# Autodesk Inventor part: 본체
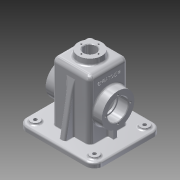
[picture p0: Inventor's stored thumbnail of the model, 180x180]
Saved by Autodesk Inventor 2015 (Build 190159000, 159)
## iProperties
Created: 2016-02
Part Number: 본체
Material: 알루미늄 6061
Document SubType Name: Modeling
Designer: Administrator
Density: 2.7 g/cm^3
Appearance: 알루미늄 - 평지
Mass: 856.212 g
Surface Area: 918.664 cm^2
Volume: 317.116 cm^3
Author: Administrator
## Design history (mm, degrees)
sketch "스케치1"
  geometry: L1 (-65, -57.5)-(65, -57.5); L2 (65, -57.5)-(65, 57.5); L3 (65, 57.5)-(-65, 57.5); L4 (-65, 57.5)-(-65, -57.5); L5 (-65, -57.5)-(65, 57.5); L6 (65, -57.5)-(-65, 57.5); 1 further point
  constraints: 12 end point, 2 midpoint, 2 parallel, 1 horizontal, 1 perpendicular
  dimensions: "d0" = 130 distance of L2.end L3.end; "d1" = 115 distance of L1.end L2.end
extrude "돌출1" new body sketch "스케치1" distance "d2" = 8; taper "d3" = 0 deg
sketch "스케치2"
  geometry: L1 (-60, -52.5)-(60, -52.5); L2 (60, -52.5)-(60, 52.5); L3 (60, 52.5)-(-60, 52.5); L4 (-60, 52.5)-(-60, -52.5); L5 (-60, -52.5)-(60, 52.5); L6 (60, -52.5)-(-60, 52.5); 1 further point
  constraints: 12 end point, 2 midpoint, 2 parallel, 1 horizontal, 1 perpendicular
  dimensions: "d4" = 120 distance of L2.end L3.end; "d5" = 105 distance of L1.end L2.end
extrude "돌출2" join sketch "스케치2" distance "d6" = 2; taper "d7" = 0 deg
sketch "스케치4"
  geometry: L1 (-65, -57.5)-(-65, 57.5) reference; L2 (-65, 57.5)-(65, 57.5) reference; L3 (65, 57.5)-(65, -57.5) reference; L4 (65, -57.5)-(-65, -57.5) reference; L5 (-32.5, -32.5)-(32.5, -32.5); L6 (32.5, -32.5)-(32.5, 32.5); L7 (32.5, 32.5)-(-32.5, 32.5); L8 (-32.5, 32.5)-(-32.5, -32.5); L9 (-32.5, -32.5)-(32.5, 32.5); L10 (32.5, -32.5)-(-32.5, 32.5); L11 (-5, 32.5)-(-5, 47.5); L12 (-5, 47.5)-(5, 47.5); L13 (5, 47.5)-(5, 32.5); L14 (-5, -32.5)-(-5, -47.5); L15 (-5, -47.5)-(5, -47.5); L16 (5, -47.5)-(5, -32.5); L17 (32.5, 3)-(42.5, 3); L18 (42.5, 3)-(42.5, -3); L19 (42.5, -3)-(32.5, -3); L20 (-32.5, 3)-(-42.5, 3); L21 (-42.5, 3)-(-42.5, -3); L22 (-42.5, -3)-(-32.5, -3); 8 further points
  constraints: 36 end point, 9 midpoint, 8 perpendicular, 8 point on line, 4 horizontal, 2 horizontal alignment, 2 parallel, 2 vertical, 2 vertical alignment
  dimensions: "d8" = 65 distance of L6.end L7.end; "d9" = 65 distance of L5.end L6.end; "d10" = 15 distance between parallel lines of L7 L12; "d11" = 10 distance of L11.end L12.end; "d12" = 15 distance between parallel lines of L15 L5; "d13" = 10 distance of L14.end L15.end; "d14" = 10 distance between parallel lines of L6 L18; "d15" = 6 distance of L17.end L18.end; "d16" = 6 distance of L20.end L21.end; "d17" = 10 distance between parallel lines of L21 L8
  node "절단 모서리 투영1"
extrude "돌출3" join sketch "스케치4" distance "d18" = 67.5; taper "d19" = 0 deg
extrude "돌출4" join sketch "스케치4" distance "d20" = 60; taper "d21" = 0 deg
sketch "스케치5"
  geometry: L1 (-75.5, -20)-(-77.5, -20) reference; L2 (-77.5, -20)-(-77.5, 85) reference; L3 (-77.5, 85)-(-75.5, 85) reference; L4 (-75.5, 85)-(-75.5, 90) reference; L5 (-75.5, 90)-(-67.5, 90) reference; L6 (-67.5, 90)-(-67.5, 65) reference; L7 (-67.5, 65)-(-67.5, 35.5) reference; L8 (-67.5, 35.5)-(-7.5, 35.5) reference; L9 (-7.5, 35.5)-(-7.5, 29.5) reference; L10 (-7.5, 29.5)-(-67.5, 29.5) reference; L11 (-67.5, 29.5)-(-67.5, 0) reference; L12 (-67.5, 0)-(-67.5, -25) reference; L13 (-67.5, -25)-(-75.5, -25) reference; L14 (-75.5, -25)-(-75.5, -20) reference; L15 (-67.5, 65)-(0, 65) reference; L16 (0, 65)-(0, 0) reference; L17 (0, 0)-(-67.5, 0) reference; C1 r 27.5 at (-22.5, 32.5); 1 further point
  constraints: 1 centre point, 1 horizontal alignment
  dimensions: "d22" = 55 diameter of C1; "d124" = 53 distance of point (-75.5, 32.5) C1.centre
extrude "돌출5" join sketch "스케치5" distance "d23" = 15; taper "d25" = 0 deg; dims "d24" = 80, "d26" = 0
sketch "스케치6"
  geometry: L1 (-32.5, -15.811)-(-47.5, -15.811) reference; L2 (-32.5, 15.811)-(-32.5, 32.5) reference; L3 (-32.5, -32.5)-(-32.5, -15.811) reference; L4 (32.5, -32.5)-(-32.5, -32.5) reference; L5 (32.5, -15.811)-(32.5, -32.5) reference; L6 (-32.5, 32.5)-(32.5, 32.5) reference; L7 (32.5, 32.5)-(32.5, 15.811) reference; L8 (-32.5, -32.5)-(32.5, -32.5); L9 (32.5, -32.5)-(32.5, 32.5); L10 (32.5, 32.5)-(-32.5, 32.5); L11 (-32.5, 32.5)-(-32.5, -32.5); L12 (-32.5, -32.5)-(32.5, 32.5); L13 (32.5, -32.5)-(-32.5, 32.5); L14 (-47.5, 15.811)-(-32.5, 15.811) reference; L15 (-32.5, 15.811)-(32.5, 15.811) reference; L16 (32.5, 15.811)-(47.5, 15.811) reference; L17 (47.5, 15.811)-(47.5, -15.811) reference; L18 (47.5, -15.811)-(32.5, -15.811) reference; L19 (32.5, -15.811)-(-32.5, -15.811) reference; L20 (-47.5, -15.811)-(-47.5, 15.811) reference; 2 further points
  constraints: 12 end point, 2 midpoint, 2 parallel, 1 horizontal, 1 perpendicular
extrude "돌출6" join sketch "스케치6" distance "d27" = 32.5; taper "d28" = 0 deg
sketch "스케치7"
  geometry: L1 (-32.5, -32.5)-(-32.5, 32.5) reference; L2 (-32.5, 32.5)-(32.5, 32.5) reference; L3 (32.5, 32.5)-(32.5, -32.5) reference; L4 (32.5, -32.5)-(-32.5, -32.5) reference; C1 r 20 at (0, 0); 1 further point
  constraints: 1 centre point, 1 coincident
  dimensions: "d29" = 40 diameter of C1
extrude "돌출7" join sketch "스케치7" distance "d30" = 10; taper "d31" = 0 deg
extrude "돌출8" join sketch "스케치4" distance "d32" = 110; taper "d33" = 0 deg
feature "면 기울기1" dims angle "d34" = 10 deg
feature "면 기울기2" dims angle "d35" = 10 deg
sketch "스케치10"
  geometry: L1 (-60, -52.5)-(-60, 52.5) reference; L2 (-60, 52.5)-(60, 52.5) reference; L3 (60, 52.5)-(60, -52.5) reference; L4 (60, -52.5)-(-60, -52.5) reference; L5 (27.5, 27.5)-(-27.5, 27.5); L6 (-27.5, 27.5)-(-27.5, -27.5); L7 (-27.5, -27.5)-(27.5, -27.5); L8 (27.5, -27.5)-(27.5, 27.5); L9 (27.5, 27.5)-(-27.5, -27.5); L10 (-27.5, 27.5)-(27.5, -27.5); 1 further point
  constraints: 12 end point, 2 midpoint, 2 parallel, 1 horizontal, 1 perpendicular
  dimensions: "d36" = 55 distance of L6.end L7.end; "d37" = 55 distance of L5.end L6.end
extrude "돌출9" cut sketch "스케치10" distance "d38" = 105; taper "d39" = 0 deg
sketch "스케치11"
  geometry: L1 (-53, -52.5)-(-55, -52.5) reference; L2 (-55, -52.5)-(-55, 52.5) reference; L3 (-55, 52.5)-(-53, 52.5) reference; L4 (-53, 52.5)-(-53, 57.5) reference; L5 (-53, 57.5)-(-45, 57.5) reference; L6 (-45, 57.5)-(-45, -57.5) reference; L7 (-45, -57.5)-(-53, -57.5) reference; L8 (-53, -57.5)-(-53, -52.5) reference; C1 r 27.5 at (0, 0) reference; C2 r 17.5 at (0, 0); 1 further point
  constraints: 1 centre point, 1 coincident
  dimensions: "d40" = 35 diameter of C2
extrude "돌출10" cut sketch "스케치11" distance "d41" = 17; taper "d42" = 0 deg
sketch "스케치12"
  geometry: L1 (55, -52.5)-(53, -52.5) reference; L2 (53, -52.5)-(53, -57.5) reference; L3 (53, -57.5)-(45, -57.5) reference; L4 (45, -57.5)-(45, 57.5) reference; L5 (45, 57.5)-(53, 57.5) reference; L6 (53, 57.5)-(53, 52.5) reference; L7 (53, 52.5)-(55, 52.5) reference; L8 (55, 52.5)-(55, -52.5) reference; C1 r 27.5 at (0, 0) reference; C2 r 17.5 at (0, 0); 1 further point
  constraints: 1 centre point, 1 coincident
  dimensions: "d43" = 35 diameter of C2
extrude "돌출11" cut sketch "스케치12" distance "d44" = 17; taper "d45" = 0 deg
sketch "스케치13"
  geometry: L1 (55, -52.5)-(53, -52.5) reference; L2 (53, -52.5)-(53, -57.5) reference; L3 (53, -57.5)-(45, -57.5) reference; L4 (45, -57.5)-(45, -32.5) reference; L5 (45, -32.5)-(-55, -32.5) reference; L6 (-55, -32.5)-(-55, 32.5) reference; L7 (-55, 32.5)-(45, 32.5) reference; L8 (45, 32.5)-(45, 57.5) reference; L9 (45, 57.5)-(53, 57.5) reference; L10 (53, 57.5)-(53, 52.5) reference; L11 (53, 52.5)-(55, 52.5) reference; L12 (55, 52.5)-(55, -52.5) reference; C1 r 17.5 at (0, 0) reference; C2 r 15 at (0, 0); 1 further point
  constraints: 1 centre point, 1 coincident
  dimensions: "d46" = 30 diameter of C2
extrude "돌출12" cut sketch "스케치13" stored distance "d47" = 17; taper "d48" = 0 deg
sketch "스케치14"
  geometry: C1 r 20 at (0, 0) reference; C2 r 10.5 at (0, 0); 1 further point
  constraints: 1 centre point, 1 coincident
  dimensions: "d49" = 21 diameter of C2
extrude "돌출13" cut sketch "스케치14" stored distance "d50" = 17; taper "d51" = 0 deg
sketch "스케치15"
  geometry: C1 r 10.5 at (0, 0) reference; C2 r 20 at (0, 0) reference; 5 further points
  constraints: 1 vertical alignment, 5 other
  dimensions: "d52" = 14.5 distance of point (0, 0) point (0, 14.5); "d55" = 360 deg dimension on point (0, 0) point (0, 14.5) (derived)
hole "구멍1" sketch "스케치15" at (0, 14.5), (-14.5, 0), (0, -14.5), (14.5, 0) diameter "d57" = 2.459; stored, may be unused: countersink angle "d61" = 90 deg, drill point angle "d63" = 118 deg; dims "d58" = 7, "d59" = 4, "d60" = 2, "d62" = 9
sketch "스케치16"
  geometry: L1 (-53, -52.5)-(-55, -52.5) reference; L2 (-55, -52.5)-(-55, 52.5) reference; L3 (-55, 52.5)-(-53, 52.5) reference; L4 (-53, 52.5)-(-53, 57.5) reference; L5 (-53, 57.5)-(-45, 57.5) reference; L6 (-45, 57.5)-(-45, -57.5) reference; L7 (-45, -57.5)-(-53, -57.5) reference; L8 (-53, -57.5)-(-53, -52.5) reference; C1 r 17.5 at (0, 0) reference; C2 r 27.5 at (0, 0) reference; 5 further points
  constraints: 1 horizontal alignment, 5 other
  dimensions: "d64" = 21 distance of C1.centre point (21, 0); "d67" = 360 deg dimension on C1.centre point (21, 0) (derived)
hole "구멍2" sketch "스케치16" at (21, 0), (0, 21), (-21, 0), (0, -21) diameter "d69" = 3.242; stored, may be unused: countersink angle "d73" = 90 deg, drill point angle "d75" = 118 deg; dims "d70" = 8, "d71" = 4, "d72" = 2, "d74" = 10
sketch "스케치17"
  geometry: L1 (55, -52.5)-(53, -52.5) reference; L2 (53, -52.5)-(53, -57.5) reference; L3 (53, -57.5)-(45, -57.5) reference; L4 (45, -57.5)-(45, 57.5) reference; L5 (45, 57.5)-(53, 57.5) reference; L6 (53, 57.5)-(53, 52.5) reference; L7 (53, 52.5)-(55, 52.5) reference; L8 (55, 52.5)-(55, -52.5) reference; C1 r 17.5 at (0, 0) reference; C2 r 27.5 at (0, 0) reference; 5 further points
  constraints: 1 horizontal alignment, 5 other
  dimensions: "d76" = 21 distance of C1.centre point (-21, 0); "d79" = 360 deg dimension on C1.centre point (-21, 0) (derived)
hole "구멍3" sketch "스케치17" at (-21, 0), (0, -21), (21, 0), (0, 21) diameter "d81" = 3.242; stored, may be unused: countersink angle "d85" = 90 deg, drill point angle "d87" = 118 deg; dims "d82" = 8, "d83" = 4, "d84" = 2, "d86" = 10
fillet "모깎기1" dims "d88" = 15
sketch "스케치18"
  geometry: L1 (-50, 57.5)-(50, 57.5) reference; L2 (65, 42.5)-(65, -42.5) reference; L3 (50, -57.5)-(-50, -57.5) reference; L4 (-65, -42.5)-(-65, 42.5) reference; L5 (27.5, -27.5)-(27.5, 27.5) reference; L6 (27.5, 27.5)-(-27.5, 27.5) reference; L7 (-27.5, 27.5)-(-27.5, -27.5) reference; L8 (-27.5, -27.5)-(27.5, -27.5) reference; L9 (-32.5, 3)-(-32.5, 32.5) reference; L10 (-32.5, 32.5)-(-5, 32.5) reference; L11 (-5, 32.5)-(-5, 47.5) reference; L12 (-5, 47.5)-(5, 47.5) reference; L13 (5, 47.5)-(5, 32.5) reference; L14 (5, 32.5)-(32.5, 32.5) reference; L15 (32.5, 32.5)-(32.5, 3) reference; L16 (32.5, 3)-(42.5, 3) reference; L17 (42.5, 3)-(42.5, -3) reference; L18 (42.5, -3)-(32.5, -3) reference; L19 (32.5, -3)-(32.5, -32.5) reference; L20 (32.5, -32.5)-(5, -32.5) reference; L21 (5, -32.5)-(5, -47.5) reference; L22 (5, -47.5)-(-5, -47.5) reference; L23 (-5, -47.5)-(-5, -32.5) reference; L24 (-5, -32.5)-(-32.5, -32.5) reference; L25 (-32.5, -32.5)-(-32.5, -3) reference; L26 (-32.5, -3)-(-42.5, -3) reference; L27 (-42.5, -3)-(-42.5, 3) reference; L28 (-42.5, 3)-(-32.5, 3) reference; C1 r 7.5 at (-50, 42.5); C2 r 7.5 at (50, 42.5); C3 r 7.5 at (50, -42.5); C4 r 7.5 at (-50, -42.5); A1 r 15 centre (-50, 42.5) between (-50, 57.5) and (-65, 42.5) reference; A2 r 15 centre (50, 42.5) between (65, 42.5) and (50, 57.5) reference; A3 r 15 centre (50, -42.5) between (50, -57.5) and (65, -42.5) reference; A4 r 15 centre (-50, -42.5) between (-65, -42.5) and (-50, -57.5) reference; 1 further point
  constraints: 4 centre point, 4 coincident
  dimensions: "d89" = 15 diameter of C1; "d90" = 15 diameter of C2; "d91" = 15 diameter of C3; "d92" = 15 diameter of C4
extrude "돌출14" join sketch "스케치18" distance "d93" = 3; taper "d94" = 0 deg
sketch "스케치19"
  geometry: L1 (-22.5, 15)-(-22.5, 70) reference; L2 (-22.5, 70)-(-77.5, 70) reference; L3 (-77.5, 70)-(-77.5, 15) reference; L4 (-77.5, 15)-(-22.5, 15) reference; L5 (-82.5, 45.5)-(-82.5, 75) reference; L6 (-82.5, 75)-(-55, 75) reference; L7 (-55, 75)-(-55, 89.471) reference; L8 (-55, 89.471)-(-45, 89.471) reference; L9 (-45, 89.471)-(-45, 75) reference; L10 (-45, 75)-(-17.5, 75) reference; L11 (-17.5, 75)-(-17.5, 45.5) reference; L12 (-17.5, 45.5)-(-7.5, 45.5) reference; L13 (-7.5, 45.5)-(-7.5, 39.5) reference; L14 (-7.5, 39.5)-(-17.5, 39.5) reference; L15 (-17.5, 39.5)-(-17.5, 10) reference; L16 (-17.5, 10)-(-45, 10) reference; L17 (-45, 10)-(-45, -4.471) reference; L18 (-45, -4.471)-(-55, -4.471) reference; L19 (-55, -4.471)-(-55, 10) reference; L20 (-55, 10)-(-82.5, 10) reference; L21 (-82.5, 10)-(-82.5, 39.5) reference; L22 (-82.5, 39.5)-(-92.5, 39.5) reference; L23 (-92.5, 39.5)-(-92.5, 45.5) reference; L24 (-92.5, 45.5)-(-82.5, 45.5) reference; C1 r 7.5 at (0, 0) reference; C2 r 7.5 at (-100, 85) reference; C3 r 7.5 at (0, 85) reference; C4 r 7.5 at (-100, 0) reference; C5 r 3 at (-100, 85); C6 r 3 at (0, 85); C7 r 3 at (0, 0); C8 r 3 at (-100, 0); 1 further point
  constraints: 4 centre point, 4 coincident
  dimensions: "d95" = 6 diameter of C5; "d96" = 6 diameter of C6; "d97" = 6 diameter of C7; "d98" = 6 diameter of C8
extrude "돌출15" cut sketch "스케치19" stored distance "d99" = 3; taper "d100" = 0 deg
chamfer "모따기1" distance "d101" = 1; stored, may be unused: second distance "d102" = 2, angle "d103" = 45 deg
fillet "모깎기2" dims "d104" = 0.3
fillet "모깎기4" dims "d106" = 8
fillet "모깎기6" dims "d108" = 10
fillet "모깎기7" dims "d109" = 3
fillet "모깎기8" dims "d110" = 3
fillet "모깎기9" dims "d111" = 3
feature "면 기울기3" dims angle "d112" = 5 deg
fillet "모깎기10" dims "d113" = 3
node "작업 평면1"
sketch "스케치21"
  geometry: L1 (-18, 44.5)-(-18, 4.5) reference; L2 (0, -8)-(92, -8) reference; 2 further points
  constraints: 1 other
  dimensions: "d117" = 26 distance from line of point (8, 24.5) L1; "d118" = 32.5 distance from line of L2 point (8, 24.5)
feature "엠보싱1" sketch "스케치21" dims "d8" = 65, "d9" = 65, "d10" = 15, "d11" = 10, "d12" = 15, "d13" = 10, "d14" = 10, "d15" = 6, "d16" = 6, "d17" = 10, "d119" = 0.5, "d120" = 0
fillet "모깎기11" dims "d121" = 1
fillet "모깎기12" dims "d122" = 3
fillet "모깎기13" dims "d123" = 3
node "솔리드1"
node "절단 모서리 투영2"
node "절단 모서리 투영3"
node "절단 모서리 투영4"
node "절단 모서리 투영5"
node "절단 모서리 투영6"
node "절단 모서리 투영7"
node "절단 모서리 투영8"
node "절단 모서리 투영9"
node "절단 모서리 투영10"
node "절단 모서리 투영11"
node "절단 모서리 투영12"
node "절단 모서리 투영13"
node "절단 모서리 투영14"
other parameters: "d116" = 24.25
